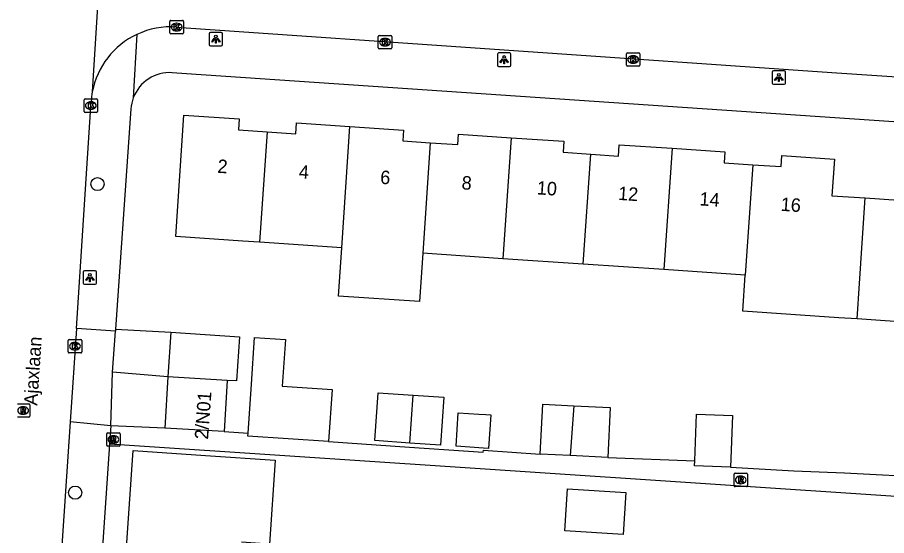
# Model space of a CAD drawing. Extents: x 161848 to 162726, y 385382 to 386521.
# Drawn here: x 162274 to 162338.6, y 385426.3 to 385464.8 of the extents above; entities that cross this region are included whole.
import ezdxf

# ---------------------------------------------------------------- set-up
doc = ezdxf.new("R2010")
doc.units = 0
for name, color, linetype in [('IMGEO_Boom', 7, 'Continuous'), ('IMGEO_Kolk', 7, 'Continuous'), ('IMGEO_Lichtpunt', 7, 'Continuous'), ('IMGEO_Openbare_ruimte_label', 7, 'Continuous'), ('IMGEO_Pand', 7, 'Continuous'), ('IMGEO_Pand_nummerreeks', 7, 'Continuous'), ('IMGEO_Rijbaan_lokaal_open', 7, 'Continuous'), ('IMGEO_Rioolput', 7, 'Continuous'), ('IMGEO_Voetpad_open', 7, 'Continuous')]:
    doc.layers.add(name, color=color, linetype=linetype)

msp = doc.modelspace()

# ---------------------------------------------------------------- linework, layer by layer
at = {"layer": 'IMGEO_Boom'}
for centre in [(162279.941, 385452.422), (162278.281, 385429.491)]:
    msp.add_circle(centre, 0.489, dxfattribs=at)
at = {"layer": 'IMGEO_Kolk'}
for p, q in [((162285.325, 385463.664), (162285.325, 385464.516)), ((162285.4, 385464.59), (162286.252, 385464.59)), ((162285.813, 385464.37), (162285.838, 385464.37)), ((162286.326, 385464.516), (162286.326, 385463.664)), ((162286.252, 385463.59), (162285.4, 385463.59)), ((162285.836, 385463.81), (162285.811, 385463.81)), ((162300.883, 385463.473), (162301.735, 385463.473)), ((162300.808, 385462.547), (162300.808, 385463.399)), ((162301.296, 385463.253), (162301.321, 385463.253)), ((162301.809, 385463.399), (162301.809, 385462.547)), ((162301.735, 385462.473), (162300.883, 385462.473)), ((162301.319, 385462.693), (162301.294, 385462.693)), ((162319.319, 385462.18), (162320.171, 385462.18)), ((162319.244, 385461.254), (162319.244, 385462.106)), ((162319.732, 385461.96), (162319.757, 385461.96)), ((162320.245, 385462.106), (162320.245, 385461.254)), ((162320.171, 385461.18), (162319.319, 385461.18)), ((162319.755, 385461.4), (162319.73, 385461.4)), ((162278.951, 385457.828), (162278.951, 385458.68)), ((162279.026, 385458.754), (162279.878, 385458.754)), ((162279.439, 385458.534), (162279.464, 385458.534)), ((162279.952, 385458.68), (162279.952, 385457.828)), ((162279.878, 385457.754), (162279.026, 385457.754)), ((162279.462, 385457.974), (162279.437, 385457.974)), ((162277.843, 385440.869), (162278.695, 385440.869)), ((162277.768, 385439.943), (162277.768, 385440.795)), ((162278.256, 385440.649), (162278.281, 385440.649)), ((162278.769, 385440.795), (162278.769, 385439.943)), ((162278.695, 385439.869), (162277.843, 385439.869)), ((162278.279, 385440.089), (162278.254, 385440.089))]:
    msp.add_line(p, q, dxfattribs=at)
for points in [[(162285.325, 385463.664), (162285.325, 385464.516)], [(162285.4, 385464.59), (162286.252, 385464.59)], [(162285.646, 385464.29), (162285.769, 385464.29), (162285.769, 385464.139), (162285.899, 385464.29), (162286.063, 385464.29), (162285.917, 385464.139), (162286.07, 385463.89), (162285.918, 385463.89), (162285.833, 385464.054), (162285.769, 385463.987), (162285.769, 385463.89), (162285.646, 385463.89), (162285.646, 385464.29)], [(162286.326, 385464.516), (162286.326, 385463.664)], [(162286.252, 385463.59), (162285.4, 385463.59)], [(162300.883, 385463.473), (162301.735, 385463.473)], [(162300.808, 385462.547), (162300.808, 385463.399)], [(162301.129, 385463.173), (162301.252, 385463.173), (162301.252, 385463.022), (162301.382, 385463.173), (162301.546, 385463.173), (162301.4, 385463.022), (162301.553, 385462.773), (162301.401, 385462.773), (162301.316, 385462.937), (162301.252, 385462.87), (162301.252, 385462.773), (162301.129, 385462.773), (162301.129, 385463.173)], [(162301.809, 385463.399), (162301.809, 385462.547)], [(162301.735, 385462.473), (162300.883, 385462.473)], [(162319.319, 385462.18), (162320.171, 385462.18)], [(162319.244, 385461.254), (162319.244, 385462.106)], [(162319.565, 385461.88), (162319.688, 385461.88), (162319.688, 385461.729), (162319.818, 385461.88), (162319.982, 385461.88), (162319.836, 385461.729), (162319.989, 385461.48), (162319.837, 385461.48), (162319.752, 385461.644), (162319.688, 385461.577), (162319.688, 385461.48), (162319.565, 385461.48), (162319.565, 385461.88)], [(162320.245, 385462.106), (162320.245, 385461.254)], [(162320.171, 385461.18), (162319.319, 385461.18)], [(162278.951, 385457.828), (162278.951, 385458.68)], [(162279.026, 385458.754), (162279.878, 385458.754)], [(162279.272, 385458.454), (162279.395, 385458.454), (162279.395, 385458.303), (162279.525, 385458.454), (162279.689, 385458.454), (162279.543, 385458.303), (162279.696, 385458.054), (162279.544, 385458.054), (162279.459, 385458.218), (162279.395, 385458.151), (162279.395, 385458.054), (162279.272, 385458.054), (162279.272, 385458.454)], [(162279.952, 385458.68), (162279.952, 385457.828)], [(162279.878, 385457.754), (162279.026, 385457.754)], [(162277.843, 385440.869), (162278.695, 385440.869)], [(162277.768, 385439.943), (162277.768, 385440.795)], [(162278.089, 385440.569), (162278.212, 385440.569), (162278.212, 385440.418), (162278.342, 385440.569), (162278.506, 385440.569), (162278.36, 385440.418), (162278.513, 385440.169), (162278.361, 385440.169), (162278.276, 385440.333), (162278.212, 385440.266), (162278.212, 385440.169), (162278.089, 385440.169), (162278.089, 385440.569)], [(162278.769, 385440.795), (162278.769, 385439.943)], [(162278.695, 385439.869), (162277.843, 385439.869)]]:
    msp.add_lwpolyline(points, dxfattribs=at)
for centre, start, end in [((162285.402, 385464.514), 91.55205, 178.44795), ((162285.402, 385464.514), 91.55205, 178.44795), ((162286.25, 385464.514), 1.55205, 88.44795), ((162286.25, 385464.514), 1.55205, 88.44795), ((162285.402, 385463.666), 181.55205, 268.44795), ((162285.402, 385463.666), 181.55205, 268.44795), ((162286.25, 385463.666), 271.55205, 358.44795), ((162286.25, 385463.666), 271.55205, 358.44795), ((162300.885, 385463.397), 91.55205, 178.44795), ((162300.885, 385463.397), 91.55205, 178.44795), ((162301.733, 385463.397), 1.55205, 88.44795), ((162301.733, 385463.397), 1.55205, 88.44795), ((162300.885, 385462.549), 181.55205, 268.44795), ((162300.885, 385462.549), 181.55205, 268.44795), ((162301.733, 385462.549), 271.55205, 358.44795), ((162301.733, 385462.549), 271.55205, 358.44795), ((162319.321, 385462.104), 91.55205, 178.44795), ((162319.321, 385462.104), 91.55205, 178.44795), ((162320.169, 385462.104), 1.55205, 88.44795), ((162320.169, 385462.104), 1.55205, 88.44795), ((162319.321, 385461.256), 181.55205, 268.44795), ((162319.321, 385461.256), 181.55205, 268.44795), ((162320.169, 385461.256), 271.55205, 358.44795), ((162320.169, 385461.256), 271.55205, 358.44795), ((162279.028, 385458.678), 91.55205, 178.44795), ((162279.028, 385458.678), 91.55205, 178.44795), ((162279.876, 385458.678), 1.55205, 88.44795), ((162279.876, 385458.678), 1.55205, 88.44795), ((162279.028, 385457.83), 181.55205, 268.44795), ((162279.028, 385457.83), 181.55205, 268.44795), ((162279.876, 385457.83), 271.55205, 358.44795), ((162279.876, 385457.83), 271.55205, 358.44795), ((162277.845, 385440.793), 91.55205, 178.44795), ((162277.845, 385440.793), 91.55205, 178.44795), ((162278.693, 385440.793), 1.55205, 88.44795), ((162278.693, 385440.793), 1.55205, 88.44795), ((162277.845, 385439.945), 181.55205, 268.44795), ((162277.845, 385439.945), 181.55205, 268.44795), ((162278.693, 385439.945), 271.55205, 358.44795), ((162278.693, 385439.945), 271.55205, 358.44795)]:
    msp.add_arc(centre, 0.0765, start, end, dxfattribs=at)
for centre, major_axis, ratio, start_param, end_param in [((162285.812, 385464.09), (-0.387, 0.002), 0.722429, 4.712389, 7.853982), ((162285.837, 385464.09), (-0.39, 0.002), 0.717154, 1.570796, 4.712389), ((162301.295, 385462.973), (-0.387, 0.002), 0.722429, 4.712389, 7.853982), ((162301.32, 385462.973), (-0.39, 0.002), 0.717154, 1.570796, 4.712389), ((162319.731, 385461.68), (-0.387, 0.002), 0.722429, 4.712389, 7.853982), ((162319.756, 385461.68), (-0.39, 0.002), 0.717154, 1.570796, 4.712389), ((162279.438, 385458.254), (-0.387, 0.002), 0.722429, 4.712389, 7.853982), ((162279.463, 385458.254), (-0.39, 0.002), 0.717154, 1.570796, 4.712389), ((162278.255, 385440.369), (-0.387, 0.002), 0.722429, 4.712389, 7.853982), ((162278.28, 385440.369), (-0.39, 0.002), 0.717154, 1.570796, 4.712389)]:
    msp.add_ellipse(centre, major_axis=major_axis, ratio=ratio, start_param=start_param, end_param=end_param, dxfattribs=at)
at = {"layer": 'IMGEO_Lichtpunt'}
for p, q in [((162288.242, 385463.594), (162288.242, 385462.787)), ((162288.242, 385463.594), (162288.242, 385462.787)), ((162289.144, 385463.689), (162288.336, 385463.689)), ((162289.144, 385463.689), (162288.336, 385463.689)), ((162289.238, 385462.787), (162289.238, 385463.594)), ((162289.238, 385462.787), (162289.238, 385463.594)), ((162288.336, 385462.693), (162289.144, 385462.693)), ((162288.336, 385462.693), (162289.144, 385462.693)), ((162309.658, 385462.072), (162309.658, 385461.265)), ((162309.658, 385462.072), (162309.658, 385461.265)), ((162310.56, 385462.167), (162309.752, 385462.167)), ((162310.56, 385462.167), (162309.752, 385462.167)), ((162310.654, 385461.265), (162310.654, 385462.072)), ((162310.654, 385461.265), (162310.654, 385462.072)), ((162309.752, 385461.171), (162310.56, 385461.171)), ((162309.752, 385461.171), (162310.56, 385461.171)), ((162330.07, 385460.74), (162330.07, 385459.933)), ((162330.07, 385460.74), (162330.07, 385459.933)), ((162330.972, 385460.835), (162330.164, 385460.835)), ((162330.972, 385460.835), (162330.164, 385460.835)), ((162331.066, 385459.933), (162331.066, 385460.74)), ((162331.066, 385459.933), (162331.066, 385460.74)), ((162330.164, 385459.839), (162330.972, 385459.839)), ((162330.164, 385459.839), (162330.972, 385459.839)), ((162278.88, 385445.873), (162278.88, 385445.066)), ((162278.88, 385445.873), (162278.88, 385445.066)), ((162279.782, 385445.968), (162278.974, 385445.968)), ((162279.782, 385445.968), (162278.974, 385445.968)), ((162279.876, 385445.066), (162279.876, 385445.873)), ((162279.876, 385445.066), (162279.876, 385445.873)), ((162278.974, 385444.972), (162279.782, 385444.972)), ((162278.974, 385444.972), (162279.782, 385444.972))]:
    msp.add_line(p, q, dxfattribs=at)
for points in [[(162288.616, 385463.258), (162288.655, 385463.23), (162288.467, 385462.968), (162288.429, 385462.995), (162288.616, 385463.258)], [(162288.718, 385463.21), (162288.765, 385463.21), (162288.765, 385462.888), (162288.718, 385462.888), (162288.718, 385463.21)], [(162288.828, 385463.23), (162288.866, 385463.257), (162289.053, 385462.995), (162289.014, 385462.967), (162288.828, 385463.23)], [(162310.032, 385461.736), (162310.071, 385461.708), (162309.883, 385461.446), (162309.845, 385461.473), (162310.032, 385461.736)], [(162310.134, 385461.688), (162310.181, 385461.688), (162310.181, 385461.366), (162310.134, 385461.366), (162310.134, 385461.688)], [(162310.244, 385461.708), (162310.282, 385461.735), (162310.469, 385461.473), (162310.43, 385461.445), (162310.244, 385461.708)], [(162330.444, 385460.404), (162330.483, 385460.376), (162330.295, 385460.114), (162330.257, 385460.141), (162330.444, 385460.404)], [(162330.546, 385460.356), (162330.593, 385460.356), (162330.593, 385460.034), (162330.546, 385460.034), (162330.546, 385460.356)], [(162330.656, 385460.376), (162330.694, 385460.403), (162330.881, 385460.141), (162330.842, 385460.113), (162330.656, 385460.376)], [(162279.254, 385445.537), (162279.293, 385445.509), (162279.105, 385445.247), (162279.067, 385445.274), (162279.254, 385445.537)], [(162279.356, 385445.489), (162279.403, 385445.489), (162279.403, 385445.167), (162279.356, 385445.167), (162279.356, 385445.489)], [(162279.466, 385445.509), (162279.504, 385445.536), (162279.691, 385445.274), (162279.652, 385445.246), (162279.466, 385445.509)]]:
    msp.add_lwpolyline(points, dxfattribs=at)
for centre in [(162288.741, 385463.392), (162310.157, 385461.87), (162330.569, 385460.538), (162279.379, 385445.671)]:
    msp.add_circle(centre, 0.0994, dxfattribs=at)
for centre, start, end in [((162288.336, 385463.594), 90, 180), ((162288.336, 385463.594), 90, 180), ((162289.144, 385463.594), 0, 90), ((162289.144, 385463.594), 0, 90), ((162288.336, 385462.787), 180, 270), ((162288.336, 385462.787), 180, 270), ((162289.144, 385462.787), 270, 0), ((162289.144, 385462.787), 270, 360), ((162309.752, 385462.072), 90, 180), ((162309.752, 385462.072), 90, 180), ((162310.56, 385462.072), 0, 90), ((162310.56, 385462.072), 0, 90), ((162309.752, 385461.265), 180, 270), ((162309.752, 385461.265), 180, 270), ((162310.56, 385461.265), 270, 0), ((162310.56, 385461.265), 270, 360), ((162330.164, 385460.74), 90, 180), ((162330.164, 385460.74), 90, 180), ((162330.972, 385460.74), 0, 90), ((162330.972, 385460.74), 0, 90), ((162330.164, 385459.933), 180, 270), ((162330.164, 385459.933), 180, 270), ((162330.972, 385459.933), 270, 0), ((162330.972, 385459.933), 270, 360), ((162278.974, 385445.873), 90, 180), ((162278.974, 385445.873), 90, 180), ((162279.782, 385445.873), 0, 90), ((162279.782, 385445.873), 0, 90), ((162278.974, 385445.066), 180, 270), ((162278.974, 385445.066), 180, 270), ((162279.782, 385445.066), 270, 0), ((162279.782, 385445.066), 270, 360)]:
    msp.add_arc(centre, 0.0946, start, end, dxfattribs=at)
at = {"layer": 'IMGEO_Pand'}
for points in [[(162291.99, 385448.097), (162290.744, 385448.181), (162285.755, 385448.518), (162286.365, 385457.543), (162290.48, 385457.265), (162290.425, 385456.449), (162292.548, 385456.305)], [(162292.548, 385456.305), (162294.67, 385456.162), (162294.724, 385456.969), (162298.702, 385456.7)], [(162298.089, 385447.685), (162298.702, 385456.7)], [(162298.702, 385456.7), (162302.681, 385456.431), (162302.628, 385455.635), (162304.668, 385455.497)], [(162292.548, 385456.305), (162291.99, 385448.097)], [(162304.668, 385455.497), (162306.707, 385455.36), (162306.759, 385456.131), (162310.68, 385455.866)], [(162310.68, 385455.866), (162310.07, 385446.875)], [(162310.68, 385455.866), (162314.601, 385455.601), (162314.546, 385454.783), (162316.598, 385454.644)], [(162304.668, 385455.497), (162304.109, 385447.278)], [(162316.598, 385454.644), (162318.648, 385454.506), (162318.705, 385455.35), (162322.638, 385455.084)], [(162322.638, 385455.084), (162322.026, 385446.067)], [(162322.638, 385455.084), (162326.569, 385454.819), (162326.514, 385454.003), (162328.63, 385453.86)], [(162316.043, 385446.472), (162316.598, 385454.644)], [(162328.63, 385453.86), (162330.743, 385453.717), (162330.799, 385454.545), (162334.7, 385454.282), (162334.516, 385451.56), (162336.992, 385451.392)], [(162328.63, 385453.86), (162328.073, 385445.659)], [(162336.992, 385451.392), (162339.469, 385451.225), (162339.657, 385453.996), (162343.668, 385453.725), (162343.608, 385452.839), (162345.731, 385452.695)], [(162336.396, 385442.4), (162336.571, 385445.037), (162336.992, 385451.392)], [(162298.089, 385447.685), (162291.99, 385448.097)], [(162304.109, 385447.278), (162303.865, 385443.686), (162297.845, 385444.093), (162298.089, 385447.685)], [(162310.07, 385446.875), (162304.109, 385447.278)], [(162316.043, 385446.472), (162310.07, 385446.875)], [(162322.026, 385446.067), (162316.043, 385446.472)], [(162328.073, 385445.659), (162322.026, 385446.067)], [(162336.396, 385442.4), (162335.029, 385442.492), (162327.89, 385442.972), (162328.073, 385445.659)], [(162345.172, 385444.456), (162341.069, 385444.732), (162340.934, 385442.094), (162336.396, 385442.4)], [(162285.399, 385441.414), (162285.178, 385438.091)], [(162285.399, 385441.414), (162290.488, 385441.076), (162290.269, 385437.789), (162289.577, 385437.83)], [(162291.136, 385433.902), (162291.384, 385437.556), (162291.62, 385441.027), (162293.907, 385440.872), (162293.672, 385437.4), (162297.373, 385437.149), (162297.11, 385433.289)], [(162285.178, 385438.091), (162284.958, 385434.284)], [(162289.577, 385437.83), (162285.178, 385438.091)], [(162289.577, 385437.83), (162289.351, 385434.023)], [(162303.15, 385433.176), (162300.547, 385433.352), (162300.789, 385436.917), (162303.392, 385436.74)], [(162303.392, 385436.74), (162305.679, 385436.584), (162305.437, 385433.02), (162303.15, 385433.176)], [(162303.15, 385433.176), (162303.392, 385436.74)], [(162312.84, 385432.35), (162313.027, 385436.065), (162315.328, 385435.95)], [(162315.328, 385435.95), (162315.076, 385432.238)], [(162315.328, 385435.95), (162318.039, 385435.814), (162317.852, 385432.099)], [(162308.798, 385435.286), (162309.174, 385435.261), (162309.005, 385432.778), (162308.629, 385432.804), (162306.586, 385432.942), (162306.755, 385435.425), (162308.273, 385435.322), (162308.798, 385435.286)], [(162324.323, 385431.851), (162324.456, 385435.325), (162327.121, 385435.223), (162326.974, 385431.386)], [(162289.351, 385434.023), (162284.958, 385434.284)], [(162297.11, 385433.289), (162291.122, 385433.696), (162291.136, 385433.902)], [(162292.921, 385404.655), (162286.06, 385405.127), (162286.529, 385411.952), (162281.684, 385412.285), (162281.619, 385411.343), (162281.132, 385411.376), (162282.593, 385432.629), (162287.974, 385432.259), (162293.149, 385431.904), (162292.721, 385425.669), (162290.635, 385425.812)], [(162315.076, 385432.238), (162312.84, 385432.35)], [(162317.852, 385432.099), (162315.076, 385432.238)], [(162326.974, 385431.386), (162324.309, 385431.488), (162324.323, 385431.851)], [(162319.205, 385429.489), (162319.005, 385426.379), (162314.659, 385426.642), (162314.861, 385429.77), (162319.205, 385429.489)]]:
    msp.add_lwpolyline(points, dxfattribs=at)
at = {"layer": 'IMGEO_Rijbaan_lokaal_open'}
for points in [[(162280.633, 385476.811), (162279.56, 385459.267)], [(162285.815, 385464.092), (162334.512, 385460.716), (162340.453, 385460.328), (162358.028, 385459.18), (162427.882, 385454.643)], [(162278.372, 385441.689), (162279.472, 385458.569)], [(162278.372, 385441.689), (162277.92, 385434.749)], [(162277.92, 385434.749), (162275.656, 385401.229)]]:
    msp.add_lwpolyline(points, dxfattribs=at)
for centre, radius, start, end in [((162285.387, 385458.179), 5.928, 115.03113, 169.42294), ((162285.387, 385458.185), 5.922, 85.85953, 115.05913), ((162285.621, 385458.148), 6.163, 169.54246, 176.08629)]:
    msp.add_arc(centre, radius, start, end, dxfattribs=at)
at = {"layer": 'IMGEO_Rioolput'}
for p, q in [((162273.992, 385436.089), (162274.844, 385436.089)), ((162274.405, 385435.869), (162274.43, 385435.869)), ((162274.918, 385436.015), (162274.918, 385435.163)), ((162274.844, 385435.089), (162273.992, 385435.089)), ((162274.428, 385435.309), (162274.403, 385435.309)), ((162280.626, 385433.013), (162280.626, 385433.865)), ((162280.701, 385433.939), (162281.553, 385433.939)), ((162281.627, 385433.865), (162281.627, 385433.013)), ((162281.137, 385433.159), (162281.112, 385433.159)), ((162281.114, 385433.719), (162281.139, 385433.719)), ((162281.553, 385432.939), (162280.701, 385432.939)), ((162327.24, 385430.008), (162327.24, 385430.86)), ((162327.315, 385430.934), (162328.167, 385430.934)), ((162327.728, 385430.714), (162327.753, 385430.714)), ((162328.241, 385430.86), (162328.241, 385430.008)), ((162328.167, 385429.934), (162327.315, 385429.934)), ((162327.751, 385430.154), (162327.726, 385430.154))]:
    msp.add_line(p, q, dxfattribs=at)
for points in [[(162273.992, 385436.089), (162274.844, 385436.089)], [(162274.506, 385435.787), (162274.254, 385435.789), (162274.254, 385435.389)], [(162274.432, 385435.708), (162274.378, 385435.708), (162274.378, 385435.627)], [(162274.918, 385436.015), (162274.918, 385435.163)], [(162274.844, 385435.089), (162273.992, 385435.089)], [(162274.254, 385435.389), (162274.378, 385435.389), (162274.378, 385435.551), (162274.389, 385435.551)], [(162274.378, 385435.627), (162274.43, 385435.627)], [(162274.436, 385435.522), (162274.507, 385435.389), (162274.647, 385435.389), (162274.582, 385435.515)], [(162280.626, 385433.013), (162280.626, 385433.865)], [(162280.701, 385433.939), (162281.553, 385433.939)], [(162281.627, 385433.865), (162281.627, 385433.013)], [(162281.215, 385433.637), (162280.963, 385433.639), (162280.963, 385433.239)], [(162280.963, 385433.239), (162281.087, 385433.239), (162281.087, 385433.401), (162281.098, 385433.401)], [(162281.141, 385433.558), (162281.087, 385433.558), (162281.087, 385433.477)], [(162281.087, 385433.477), (162281.139, 385433.477)], [(162281.145, 385433.372), (162281.216, 385433.239), (162281.356, 385433.239), (162281.291, 385433.365)], [(162281.553, 385432.939), (162280.701, 385432.939)], [(162327.24, 385430.008), (162327.24, 385430.86)], [(162327.315, 385430.934), (162328.167, 385430.934)], [(162327.829, 385430.632), (162327.577, 385430.634), (162327.577, 385430.234)], [(162327.755, 385430.553), (162327.701, 385430.553), (162327.701, 385430.472)], [(162328.241, 385430.86), (162328.241, 385430.008)], [(162328.167, 385429.934), (162327.315, 385429.934)], [(162327.577, 385430.234), (162327.701, 385430.234), (162327.701, 385430.396), (162327.712, 385430.396)], [(162327.701, 385430.472), (162327.753, 385430.472)], [(162327.759, 385430.367), (162327.83, 385430.234), (162327.97, 385430.234), (162327.905, 385430.36)]]:
    msp.add_lwpolyline(points, dxfattribs=at)
for centre, radius, start, end in [((162274.438, 385435.612), 0.0964, 77.00612, 93.18647), ((162274.452, 385435.669), 0.0378, 276.66336, 79.67722), ((162274.505, 385435.677), 0.109, 350.36119, 89.41601), ((162274.842, 385436.013), 0.0765, 1.55205, 88.44795), ((162274.842, 385436.013), 0.0765, 1.55205, 88.44795), ((162274.388, 385435.498), 0.0533, 26.02933, 88.69889), ((162274.414, 385435.816), 0.19, 274.7715, 282.96867), ((162274.503, 385435.677), 0.112, 277.58423, 350.98172), ((162274.487, 385435.462), 0.108, 29.51342, 73.79051), ((162274.842, 385435.165), 0.0765, 271.55205, 358.44795), ((162274.842, 385435.165), 0.0765, 271.55205, 358.44795), ((162280.703, 385433.863), 0.0765, 91.55205, 178.44795), ((162280.703, 385433.863), 0.0765, 91.55205, 178.44795), ((162281.551, 385433.863), 0.0765, 1.55205, 88.44795), ((162281.551, 385433.863), 0.0765, 1.55205, 88.44795), ((162281.097, 385433.348), 0.0533, 26.02933, 88.69889), ((162281.123, 385433.666), 0.19, 274.7715, 282.96867), ((162281.147, 385433.462), 0.0964, 77.00612, 93.18647), ((162281.161, 385433.519), 0.0378, 276.66336, 79.67722), ((162281.214, 385433.527), 0.109, 350.36119, 89.41601), ((162281.212, 385433.527), 0.112, 277.58423, 350.98172), ((162281.196, 385433.312), 0.108, 29.51342, 73.79051), ((162280.703, 385433.015), 0.0765, 181.55205, 268.44795), ((162280.703, 385433.015), 0.0765, 181.55205, 268.44795), ((162281.551, 385433.015), 0.0765, 271.55205, 358.44795), ((162281.551, 385433.015), 0.0765, 271.55205, 358.44795), ((162327.317, 385430.858), 0.0765, 91.55205, 178.44795), ((162327.317, 385430.858), 0.0765, 91.55205, 178.44795), ((162327.761, 385430.457), 0.0964, 77.00612, 93.18647), ((162327.775, 385430.514), 0.0378, 276.66336, 79.67722), ((162327.828, 385430.522), 0.109, 350.36119, 89.41601), ((162328.165, 385430.858), 0.0765, 1.55205, 88.44795), ((162328.165, 385430.858), 0.0765, 1.55205, 88.44795), ((162327.317, 385430.01), 0.0765, 181.55205, 268.44795), ((162327.317, 385430.01), 0.0765, 181.55205, 268.44795), ((162327.711, 385430.343), 0.0533, 26.02933, 88.69889), ((162327.737, 385430.661), 0.19, 274.7715, 282.96867), ((162327.826, 385430.522), 0.112, 277.58423, 350.98172), ((162327.81, 385430.307), 0.108, 29.51342, 73.79051), ((162328.165, 385430.01), 0.0765, 271.55205, 358.44795), ((162328.165, 385430.01), 0.0765, 271.55205, 358.44795)]:
    msp.add_arc(centre, radius, start, end, dxfattribs=at)
for centre, major_axis, ratio, start_param, end_param in [((162274.404, 385435.589), (-0.387, 0.002), 0.722429, 4.712389, 7.853982), ((162274.429, 385435.589), (-0.39, 0.002), 0.717154, 1.570796, 4.712389), ((162281.113, 385433.439), (-0.387, 0.002), 0.722429, 4.712389, 7.853982), ((162281.138, 385433.439), (-0.39, 0.002), 0.717154, 1.570796, 4.712389), ((162327.727, 385430.434), (-0.387, 0.002), 0.722429, 4.712389, 7.853982), ((162327.752, 385430.434), (-0.39, 0.002), 0.717154, 1.570796, 4.712389)]:
    msp.add_ellipse(centre, major_axis=major_axis, ratio=ratio, start_param=start_param, end_param=end_param, dxfattribs=at)
at = {"layer": 'IMGEO_Voetpad_open'}
for points in [[(162282.879, 385463.55), (162282.604, 385458.839)], [(162428.108, 385451.016), (162424.152, 385451.285), (162286.568, 385460.627), (162285.504, 385460.702)], [(162282.422, 385458.009), (162281.291, 385441.643)], [(162281.28, 385441.479), (162278.372, 385441.689)], [(162281.291, 385441.643), (162281.28, 385441.479)], [(162281.291, 385441.643), (162285.399, 385441.414)], [(162281.071, 385438.454), (162281.28, 385441.479)], [(162280.93, 385434.463), (162281.071, 385438.454)], [(162285.178, 385438.091), (162281.071, 385438.454)], [(162280.93, 385434.463), (162277.92, 385434.749)], [(162280.93, 385434.463), (162280.836, 385433.091)], [(162284.958, 385434.284), (162280.93, 385434.463)], [(162289.351, 385434.023), (162291.136, 385433.902)], [(162297.11, 385433.289), (162303.13, 385432.88), (162308.609, 385432.507), (162308.618, 385432.638), (162312.84, 385432.35)], [(162280.836, 385433.091), (162278.626, 385400.728), (162278.251, 385395.589)], [(162428.958, 385423.219), (162280.836, 385433.091)], [(162317.852, 385432.099), (162324.323, 385431.851)], [(162326.974, 385431.386), (162331.696, 385431.11), (162335.438, 385430.957), (162342.062, 385430.624)]]:
    msp.add_lwpolyline(points, dxfattribs=at)
for centre, radius, start, end in [((162285.316, 385457.807), 2.901, 86.27732, 159.15718), ((162285.36, 385457.8), 2.945, 159.33851, 175.92568)]:
    msp.add_arc(centre, radius, start, end, dxfattribs=at)

# ---------------------------------------------------------------- texts
at = {"layer": 'IMGEO_Openbare_ruimte_label'}
msp.add_text('Ajaxlaan', height=1, rotation=86.21641, dxfattribs=at).set_placement((162275.469, 385435.938))
at = {"layer": 'IMGEO_Pand_nummerreeks'}
for s, rotation, p in [('2', 356.12897, (162288.834, 385453.266)), ('4', 356.12897, (162294.881, 385452.857)), ('6', 356.12897, (162300.927, 385452.447)), ('8', 356.12897, (162306.977, 385452.037)), ('10', 356.12897, (162312.564, 385451.659)), ('12', 356.12897, (162318.604, 385451.251)), ('14', 356.12897, (162324.652, 385450.841)), ('16', 356.21848, (162330.688, 385450.438)), ('2/N01', 85.79464, (162288.155, 385433.416))]:
    msp.add_text(s, height=1, rotation=rotation, dxfattribs=at).set_placement(p)

doc.saveas('drawing.dxf')
